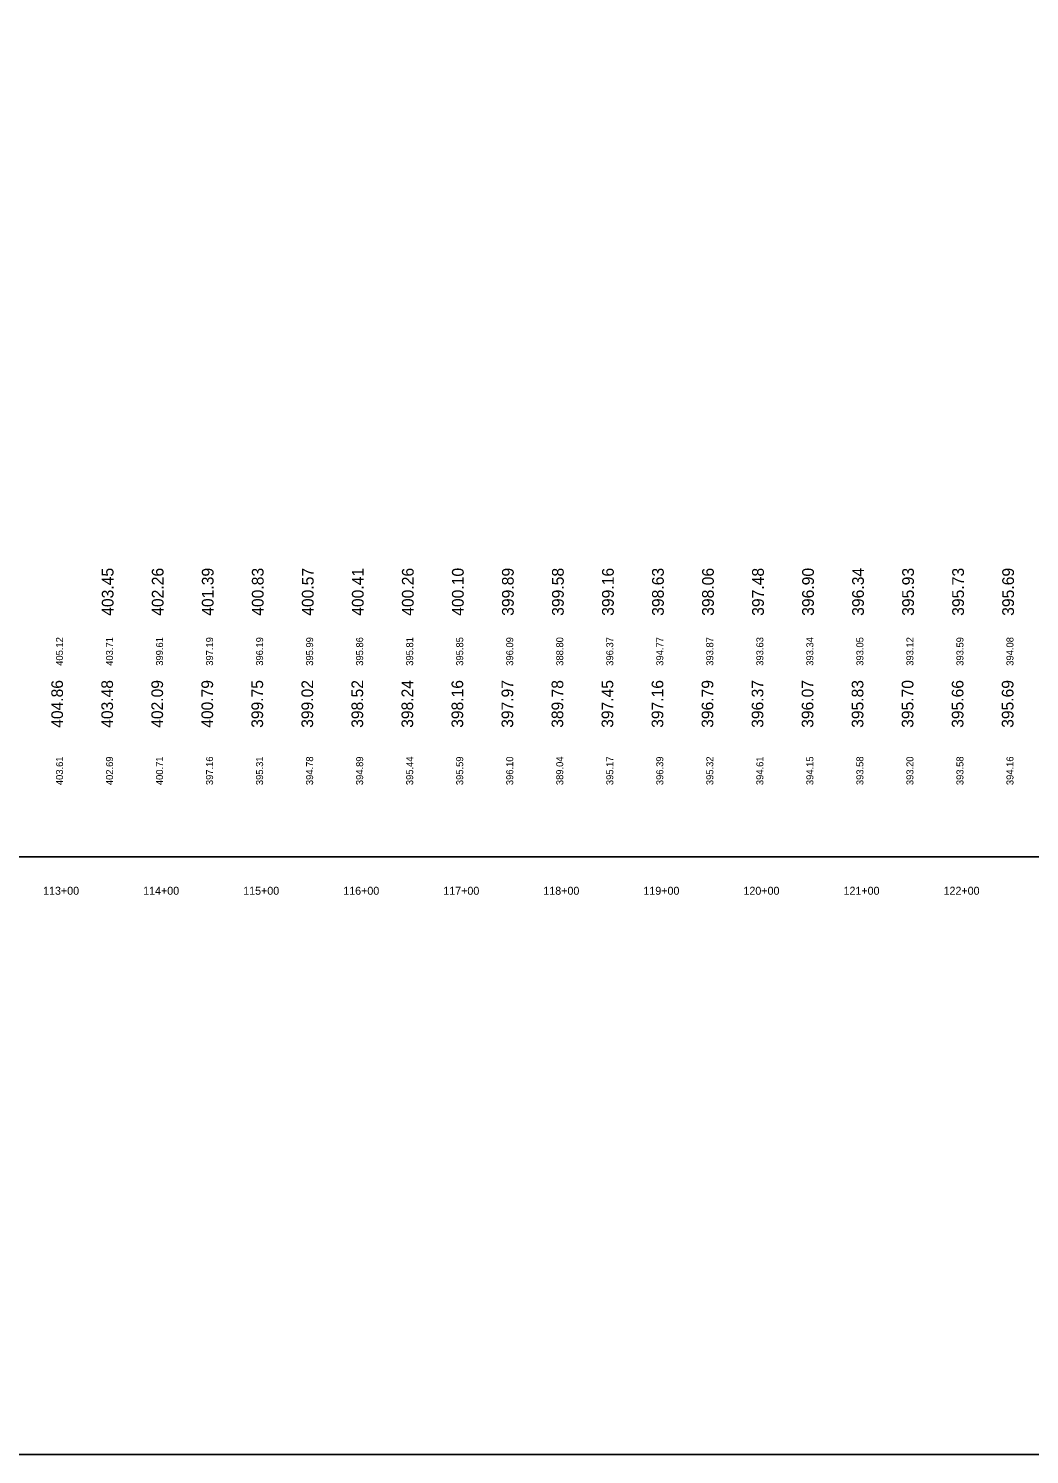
# Model space of a CAD drawing. Extents: x 2084170 to 2089570, y 1072039 to 1077242.
# Drawn here: x 2086154 to 2087155, y 1073942 to 1075367 of the extents above; entities that cross this region are included whole.
import ezdxf

# ---------------------------------------------------------------- set-up
doc = ezdxf.new("R2010")
doc.units = 0
for name, color, linetype in [('RD_DDB_StaTX', 7, 'Continuous'), ('RD_DDB_StripGrade', 7, 'Continuous'), ('RD_GPK_Profile_Cell', 7, 'Continuous'), ('RD_Sketch2', 7, 'Continuous'), ('RD_Sketch3', 7, 'Continuous'), ('RD_Sketch4', 7, 'Continuous')]:
    doc.layers.add(name, color=color, linetype=linetype)

msp = doc.modelspace()

# ---------------------------------------------------------------- linework, layer by layer
at = {"layer": 'RD_GPK_Profile_Cell'}
msp.add_line((2085189.9, 1074539.2), (2088289.9, 1074539.2), dxfattribs=at)
at = {"layer": 'RD_Sketch2'}
msp.add_lwpolyline([(2084170, 1073941.9), (2089570, 1073941.9), (2089570, 1077241.9), (2084170, 1077241.9)], close=True, dxfattribs=at)

# ---------------------------------------------------------------- texts
at = {"layer": 'RD_DDB_StaTX'}
for s, p in [('113+00', (2086169, 1074501.4)), ('114+00', (2086269, 1074501.4)), ('115+00', (2086369, 1074501.4)), ('116+00', (2086469, 1074501.4)), ('117+00', (2086569, 1074501.4)), ('118+00', (2086669, 1074501.4)), ('119+00', (2086769, 1074501.4)), ('120+00', (2086869, 1074501.4)), ('121+00', (2086969, 1074501.4)), ('122+00', (2087069, 1074501.4))]:
    msp.add_text(s, height=8, dxfattribs=at).set_placement(p)
at = {"layer": 'RD_DDB_StripGrade'}
for s, height, p in [('403.45', 11.73, (2086239.4, 1074780.2)), ('402.26', 11.73, (2086289.4, 1074780.2)), ('401.39', 11.73, (2086339.4, 1074780.2)), ('400.83', 11.73, (2086389.4, 1074780.2)), ('400.57', 11.73, (2086439.4, 1074780.2)), ('400.41', 11.73, (2086489.4, 1074780.2)), ('400.26', 11.73, (2086539.4, 1074780.2)), ('400.10', 11.73, (2086589.4, 1074780.2)), ('399.89', 11.73, (2086639.4, 1074780.2)), ('399.58', 11.73, (2086689.4, 1074780.2)), ('399.16', 11.73, (2086739.4, 1074780.2)), ('398.63', 11.73, (2086789.4, 1074780.2)), ('398.06', 11.73, (2086839.4, 1074780.2)), ('397.48', 11.73, (2086889.4, 1074780.2)), ('396.90', 11.73, (2086939.4, 1074780.2)), ('396.34', 11.73, (2086989.4, 1074780.2)), ('395.93', 11.73, (2087039.4, 1074780.2)), ('395.73', 11.73, (2087089.4, 1074780.2)), ('395.69', 11.73, (2087139.4, 1074780.2)), ('404.86', 11.67, (2086188.9, 1074668.3)), ('403.48', 11.67, (2086238.9, 1074668.3)), ('402.09', 11.67, (2086288.9, 1074668.3)), ('400.79', 11.67, (2086338.9, 1074668.3)), ('399.75', 11.67, (2086388.9, 1074668.3)), ('399.02', 11.67, (2086438.9, 1074668.3)), ('398.52', 11.67, (2086488.9, 1074668.3)), ('398.24', 11.67, (2086538.9, 1074668.3)), ('398.16', 11.67, (2086588.9, 1074668.3)), ('397.97', 11.67, (2086638.9, 1074668.3)), ('389.78', 11.67, (2086688.9, 1074668.3)), ('397.45', 11.67, (2086738.9, 1074668.3)), ('397.16', 11.67, (2086788.9, 1074668.3)), ('396.79', 11.67, (2086838.9, 1074668.3)), ('396.37', 11.67, (2086888.9, 1074668.3)), ('396.07', 11.67, (2086938.9, 1074668.3)), ('395.83', 11.67, (2086988.9, 1074668.3)), ('395.70', 11.67, (2087038.9, 1074668.3)), ('395.66', 11.67, (2087088.9, 1074668.3)), ('395.69', 11.67, (2087138.9, 1074668.3))]:
    msp.add_text(s, height=height, rotation=90, dxfattribs=at).set_placement(p)
at = {"layer": 'RD_Sketch3'}
for s, p in [('403.61', (2086188.9, 1074611)), ('402.69', (2086238.9, 1074611)), ('400.71', (2086288.9, 1074611)), ('397.16', (2086338.9, 1074611)), ('395.31', (2086388.9, 1074611)), ('394.78', (2086438.9, 1074611)), ('394.89', (2086488.9, 1074611)), ('395.44', (2086538.9, 1074611)), ('395.59', (2086588.9, 1074611)), ('396.10', (2086638.9, 1074611)), ('389.04', (2086688.9, 1074611)), ('395.17', (2086738.9, 1074611)), ('396.39', (2086788.9, 1074611)), ('395.32', (2086838.9, 1074611)), ('394.61', (2086888.9, 1074611)), ('394.15', (2086938.9, 1074611)), ('393.58', (2086988.9, 1074611)), ('393.20', (2087038.9, 1074611)), ('393.58', (2087088.9, 1074611)), ('394.16', (2087138.9, 1074611))]:
    msp.add_text(s, height=7, rotation=90, dxfattribs=at).set_placement(p)
at = {"layer": 'RD_Sketch4'}
for s, p in [('395.86', (2086488.9, 1074730.3)), ('395.85', (2086588.9, 1074730.3)), ('388.80', (2086688.9, 1074730.3)), ('393.63', (2086888.9, 1074730.3)), ('393.34', (2086938.9, 1074730.3)), ('393.05', (2086988.9, 1074730.3)), ('394.08', (2087138.9, 1074730.3)), ('405.12', (2086188.9, 1074730.3)), ('403.71', (2086238.9, 1074730.3)), ('399.61', (2086288.9, 1074730.3)), ('397.19', (2086338.9, 1074730.3)), ('396.19', (2086388.9, 1074730.3)), ('395.99', (2086438.9, 1074730.3)), ('395.81', (2086538.9, 1074730.3)), ('396.09', (2086638.9, 1074730.3)), ('396.37', (2086738.9, 1074730.3)), ('394.77', (2086788.9, 1074730.3)), ('393.87', (2086838.9, 1074730.3)), ('393.12', (2087038.9, 1074730.3)), ('393.59', (2087088.9, 1074730.3))]:
    msp.add_text(s, height=7, rotation=90, dxfattribs=at).set_placement(p)

doc.saveas('drawing.dxf')
